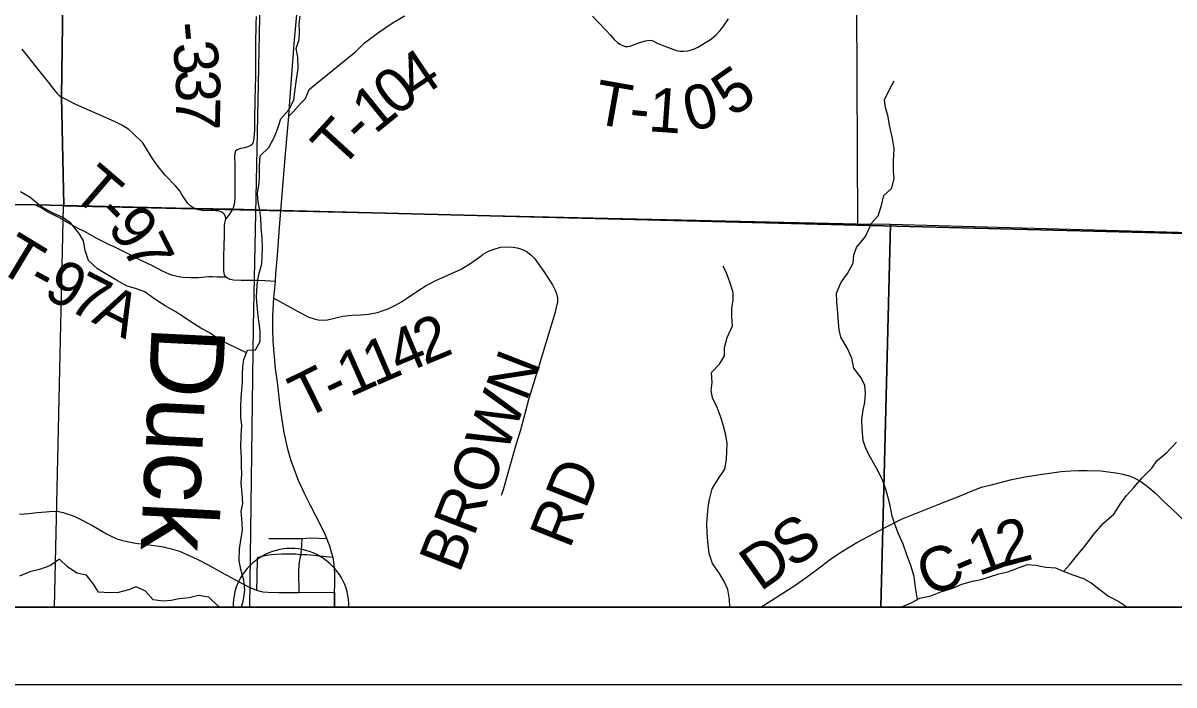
# Model space of a CAD drawing. Extents: x 0 to 34, y 0 to 22.
# Drawn here: x 26.994 to 28.471, y 14 to 14.85 of the extents above; entities that cross this region are included whole.
import ezdxf

# ---------------------------------------------------------------- set-up
doc = ezdxf.new("R2010")
doc.units = 0
for name, color, linetype in [('GM_X_Corporation', 7, 'Continuous'), ('GM_X_Corporation_Text', 7, 'Continuous'), ('GM_X_County_Road', 7, 'Continuous'), ('GM_X_County_Road_Text', 7, 'Continuous'), ('GM_X_Minor_River', 7, 'Continuous'), ('GM_X_Minor_River_Text', 7, 'Continuous'), ('GM_X_Rail_Line', 7, 'Continuous'), ('GM_X_State_Route', 7, 'Continuous'), ('GM_X_Township_Road', 7, 'Continuous'), ('GM_X_Township_Road_Text', 7, 'Continuous'), ('GM_X_Unincorporated_Location', 7, 'Continuous'), ('SH_Data', 7, 'Continuous')]:
    doc.layers.add(name, color=color, linetype=linetype)

msp = doc.modelspace()

# ---------------------------------------------------------------- linework, layer by layer
at = {"layer": 'GM_X_Corporation'}
for points in [[(26.6535, 14.621), (27.01, 14.6164), (27.046, 14.6155), (27.043, 14.755), (27.052, 15.403), (27.0676, 16.5549), (27.0694, 16.6556), (27.0775, 16.888), (27.0944, 18.0731), (27.1039, 18.5696), (27.1064, 18.6537), (27.3971, 18.6436), (28.3421, 18.6121), (28.7772, 18.6028), (29.0074, 18.5935), (29.6561, 18.5791), (29.6772, 18.5786), (30.101, 18.5701), (30.3167, 18.565), (30.3167, 20.9), (23.5167, 20.9)], [(23.5167, 14.1), (30.3167, 14.1), (30.3167, 18.565), (30.101, 18.5701), (29.6772, 18.5786), (29.6561, 18.5791), (29.0074, 18.5935), (28.7772, 18.6028), (28.3421, 18.6121), (27.3971, 18.6436), (27.1064, 18.6537), (27.1039, 18.5696), (27.0944, 18.0731), (27.0775, 16.888), (27.0694, 16.6556), (27.0676, 16.5549), (27.052, 15.403), (27.043, 14.755), (27.046, 14.6155), (27.01, 14.6164), (26.6535, 14.621)], [(27.0676, 16.5549), (27.052, 15.403), (27.043, 14.755), (27.046, 14.6155), (27.2076, 14.6118), (27.2151, 14.6117), (27.2601, 14.6106), (27.262, 14.6106), (27.3217, 14.6092), (27.3244, 14.6092), (28.7538, 14.5726), (28.7592, 14.5724), (28.9743, 14.568), (28.9779, 14.5679), (28.9904, 14.5676), (29.257, 14.5621), (29.2606, 14.562), (30.0913, 14.5411), (30.0947, 14.5411), (30.3167, 14.5373), (30.3167, 18.565)], [(26.6535, 14.621), (27.01, 14.6164), (27.046, 14.6155), (27.043, 14.755), (27.052, 15.403), (27.0676, 16.5549), (27.0694, 16.6556), (26.3378, 16.673)], [(26.0358, 14.1), (30.3167, 14.1), (30.3167, 14.5373), (30.0947, 14.5411), (30.0913, 14.5411), (29.2606, 14.562), (29.257, 14.5621), (28.9904, 14.5676), (28.9779, 14.5679), (28.9743, 14.568), (28.7592, 14.5724), (28.7538, 14.5726), (27.3244, 14.6092), (27.3217, 14.6092), (27.262, 14.6106), (27.2601, 14.6106), (27.2151, 14.6117), (27.2076, 14.6118), (27.046, 14.6155), (27.01, 14.6164), (26.6535, 14.621)]]:
    msp.add_lwpolyline(points, dxfattribs=at)
for points in [[(29.0554, 15.5858), (29.0455, 14.5648), (28.107, 14.591), (28.0653, 14.5914), (28.0603, 15.6194)], [(27.0339, 14.1), (28.0946, 14.1), (28.107, 14.591), (28.0653, 14.5914), (27.0453, 14.6145)], [(28.0946, 14.1), (29.1022, 14.1), (29.1115, 14.5644), (29.0455, 14.5648), (28.107, 14.591)]]:
    msp.add_lwpolyline(points, close=True, dxfattribs=at)
at = {"layer": 'GM_X_Corporation_Text'}
msp.add_line((27.2633, 14.1), (27.4121, 14.1), dxfattribs=at)
msp.add_arc((27.3377, 14.1008), 0.0744, 359.3562, 180.6438, dxfattribs=at)
at = {"layer": 'GM_X_County_Road'}
msp.add_line((27.3937, 14.1192), (27.3935, 14.1), dxfattribs=at)
for points in [[(27.9405, 14.1), (27.9842, 14.1276), (28.0004, 14.1392), (28.0188, 14.1529), (28.0299, 14.1613), (28.0406, 14.1687), (28.0517, 14.1758), (28.0638, 14.1831), (28.0991, 14.2019), (28.1213, 14.2127), (28.1403, 14.2206), (28.1681, 14.2318), (28.1997, 14.2439), (28.2119, 14.2493), (28.224, 14.2538), (28.2378, 14.2574), (28.2626, 14.2638), (28.2799, 14.2671), (28.2962, 14.2699), (28.3259, 14.2739), (28.3385, 14.2748), (28.3486, 14.2754), (28.3594, 14.2754), (28.3771, 14.2747), (28.396, 14.2723), (28.4053, 14.2704), (28.4131, 14.2683), (28.4199, 14.2657), (28.4283, 14.2611), (28.4385, 14.2535), (28.4465, 14.2466), (28.4576, 14.2357), (28.4674, 14.2264), (28.4869, 14.2081)], [(26.9891, 14.2192), (27.0011, 14.2203), (27.012, 14.2213), (27.0229, 14.2223), (27.0327, 14.223), (27.0395, 14.2225), (27.0454, 14.2213), (27.0502, 14.2199), (27.0555, 14.2179), (27.0601, 14.2162), (27.0645, 14.2143), (27.0821, 14.2052), (27.1011, 14.1942), (27.1077, 14.1904), (27.1143, 14.1874), (27.1202, 14.1857), (27.1275, 14.184), (27.1383, 14.1821), (27.1524, 14.1802), (27.1713, 14.1776), (27.1828, 14.1753), (27.1945, 14.1717), (27.2033, 14.1678), (27.2172, 14.1613), (27.2312, 14.1541), (27.248, 14.1449), (27.2609, 14.1378), (27.2749, 14.1303), (27.2839, 14.1255), (27.2934, 14.1218), (27.2976, 14.1204), (27.302, 14.1195), (27.308, 14.1191), (27.3217, 14.1185), (27.348, 14.1186), (27.3937, 14.1192)]]:
    msp.add_lwpolyline(points, dxfattribs=at)
at = {"layer": 'GM_X_Minor_River'}
for points in [[(27.2743, 14.1), (27.2768, 14.1092), (27.2783, 14.1217), (27.2771, 14.1346), (27.2733, 14.1483), (27.271, 14.16), (27.2717, 14.1744), (27.2735, 14.1858), (27.2754, 14.1983), (27.275, 14.2078), (27.2738, 14.2233), (27.2757, 14.2328), (27.2752, 14.2457), (27.2737, 14.2593), (27.2744, 14.2703), (27.274, 14.281), (27.274, 14.2912), (27.2735, 14.3056), (27.2739, 14.3204), (27.2746, 14.3337), (27.2734, 14.3435), (27.2734, 14.3568), (27.2737, 14.3685), (27.2745, 14.3784), (27.2756, 14.3886), (27.2755, 14.3985), (27.2759, 14.4083), (27.277, 14.4178), (27.2819, 14.4296), (27.2921, 14.4304), (27.2981, 14.441), (27.2981, 14.4547), (27.2969, 14.4645), (27.2954, 14.474), (27.2942, 14.4865), (27.2934, 14.4979), (27.2941, 14.5138), (27.2964, 14.5271), (27.3001, 14.5407), (27.3008, 14.551), (27.3012, 14.5612), (27.3008, 14.573), (27.2996, 14.5874), (27.2988, 14.5995), (27.2976, 14.6094), (27.2957, 14.62), (27.2945, 14.6309), (27.2968, 14.6442), (27.2971, 14.6537), (27.2971, 14.6662), (27.2982, 14.6791), (27.3091, 14.6898), (27.3167, 14.7034), (27.3208, 14.7148), (27.3245, 14.7266), (27.3347, 14.7384), (27.3415, 14.7505), (27.3426, 14.7619), (27.3448, 14.7771), (27.3467, 14.7915), (27.3466, 14.8059), (27.3443, 14.8169), (27.3481, 14.8286), (27.3484, 14.8393), (27.348, 14.8487), (27.3495, 14.8586)], [(28.1416, 14.1098), (28.1393, 14.1251), (28.1373, 14.1391), (28.1331, 14.1532), (28.1278, 14.1672), (28.1232, 14.1808), (28.1171, 14.194), (28.1125, 14.2065), (28.1091, 14.2168), (28.1064, 14.2304), (28.1037, 14.2418), (28.1006, 14.2528), (28.096, 14.2652), (28.0892, 14.2785), (28.0812, 14.2921), (28.0759, 14.3027), (28.072, 14.3133), (28.0705, 14.3292), (28.0701, 14.3402), (28.0719, 14.3531), (28.0742, 14.3626), (28.0749, 14.3747), (28.0741, 14.3842), (28.0695, 14.3941), (28.06, 14.4065), (28.0573, 14.4194), (28.0512, 14.4327), (28.0433, 14.4463), (28.0413, 14.4558), (28.0402, 14.4652), (28.0394, 14.4777), (28.0382, 14.4918), (28.0378, 14.5031), (28.0434, 14.5164), (28.0517, 14.5282), (28.0589, 14.5415), (28.06, 14.5521), (28.0634, 14.5616), (28.0751, 14.5757), (28.0826, 14.5928), (28.0913, 14.6023), (28.0954, 14.6156), (28.0984, 14.6281), (28.1086, 14.6376), (28.1116, 14.6501), (28.1108, 14.6596), (28.1107, 14.6729), (28.1118, 14.6888), (28.1095, 14.7013), (28.1057, 14.7187), (28.1041, 14.7293), (28.1007, 14.7411), (28.0995, 14.7509), (28.1055, 14.7634), (28.1116, 14.7756)], [(27.0182, 14.6132), (27.0152, 14.6156), (27.0029, 14.6256), (26.9906, 14.6328)], [(27.2806, 14.4265), (27.2591, 14.4367), (27.2444, 14.4443), (27.2341, 14.4514), (27.222, 14.4582), (27.2106, 14.4654), (27.1996, 14.4725), (27.189, 14.4793), (27.1761, 14.4865), (27.1617, 14.4959), (27.1503, 14.5046), (27.1381, 14.5091), (27.1275, 14.5121), (27.1131, 14.52), (27.1014, 14.5268), (27.0892, 14.5343), (27.0778, 14.5449), (27.0736, 14.5578), (27.0713, 14.5699), (27.066, 14.5797), (27.0546, 14.5934), (27.0451, 14.6001), (27.0326, 14.6058), (27.0182, 14.6132)], [(27.9008, 14.1), (27.9008, 14.1004), (27.9004, 14.1099), (27.8981, 14.1224), (27.8935, 14.133), (27.8874, 14.1432), (27.8787, 14.156), (27.8741, 14.1689), (27.8725, 14.1841), (27.8717, 14.1955), (27.8713, 14.2072), (27.872, 14.2182), (27.8731, 14.2281), (27.8746, 14.2379), (27.878, 14.2516), (27.8855, 14.2637), (27.8946, 14.2771), (27.8964, 14.2896), (27.8968, 14.2998), (27.8975, 14.31), (27.8956, 14.3207), (27.8929, 14.332), (27.8898, 14.3426), (27.8845, 14.3563), (27.8784, 14.3687), (27.8769, 14.3782), (27.878, 14.3881), (27.8772, 14.401), (27.8877, 14.412), (27.8938, 14.4223), (27.8941, 14.4332), (27.8975, 14.4462), (27.9043, 14.461), (27.9035, 14.4727), (27.9034, 14.4833), (27.9049, 14.4943), (27.9053, 14.5038), (27.9014, 14.5159), (27.8969, 14.5277), (27.8923, 14.5375)], [(28.3294, 14.1459), (28.3372, 14.1546), (28.3474, 14.1676), (28.3568, 14.1786), (28.3681, 14.1938), (28.3802, 14.2075), (28.3938, 14.2193), (28.4028, 14.2334), (28.41, 14.2432), (28.4194, 14.2535), (28.43, 14.2661), (28.4425, 14.2782), (28.4489, 14.2877), (28.4617, 14.2984), (28.4742, 14.3117)], [(27.2461, 14.1), (27.2442, 14.1011), (27.2321, 14.1129), (27.2188, 14.1147), (27.2071, 14.112), (27.1942, 14.1105), (27.184, 14.1085), (27.1738, 14.1077), (27.1609, 14.1092), (27.151, 14.1205), (27.1389, 14.1262), (27.1291, 14.122), (27.1162, 14.1189), (27.1049, 14.1181), (27.0908, 14.1192), (27.0844, 14.1294), (27.0753, 14.1408), (27.0628, 14.1434), (27.051, 14.1517), (27.0407, 14.1615), (27.0283, 14.1531), (27.015, 14.1481), (27.0025, 14.1454), (26.9893, 14.1397)], [(28.1212, 14.1), (28.1215, 14.1004), (28.1336, 14.1054), (28.1446, 14.1115), (28.1586, 14.1146), (28.1718, 14.1195), (28.1858, 14.1238), (28.1987, 14.1295), (28.2123, 14.1333), (28.2233, 14.1353), (28.2342, 14.1387), (28.246, 14.1426), (28.2577, 14.1453), (28.2721, 14.1506), (28.2827, 14.1548), (28.2933, 14.1537), (28.3065, 14.1511), (28.3186, 14.1504), (28.3285, 14.1463), (28.341, 14.1414), (28.3547, 14.1365), (28.3645, 14.1312), (28.3744, 14.1233), (28.3869, 14.1139), (28.4002, 14.1071), (28.4104, 14.1003), (28.4112, 14.1)]]:
    msp.add_lwpolyline(points, dxfattribs=at)
at = {"layer": 'GM_X_Rail_Line'}
msp.add_lwpolyline([(27.2849, 14.1), (27.2894, 14.4603), (27.296, 14.7712), (27.3019, 15.0727), (27.3033, 15.1457), (27.3034, 15.1975), (27.3156, 15.2527), (27.342, 15.317), (27.3625, 15.3837), (27.3871, 15.4458), (27.4012, 15.4983), (27.4051, 15.5497), (27.4044, 15.6175), (27.3887, 15.6715), (27.3693, 15.7118), (27.3529, 15.7652), (27.3562, 15.8103), (27.3646, 15.8502), (27.3938, 15.9037), (27.407, 16.0055), (27.4058, 16.0745), (27.3982, 16.1548), (27.3854, 16.3634)], dxfattribs=at)
at = {"layer": 'GM_X_State_Route'}
msp.add_line((27.3935, 14.1), (27.3937, 14.1192), dxfattribs=at)
for points in [[(27.3191, 14.537), (27.3203, 14.5516), (27.3228, 14.5871), (27.3246, 14.6086), (27.3301, 14.6767), (27.3348, 14.7301), (27.3353, 14.7379), (27.3418, 14.823), (27.3466, 14.8746)], [(27.3177, 14.5179), (27.3183, 14.5282), (27.3191, 14.537)], [(27.3937, 14.1192), (27.394, 14.1286), (27.3938, 14.1436), (27.3931, 14.1546), (27.3916, 14.1638), (27.3901, 14.1688), (27.3876, 14.1781), (27.386, 14.1823), (27.3837, 14.188), (27.3802, 14.196), (27.3693, 14.2178), (27.3623, 14.2314), (27.3552, 14.2457), (27.3475, 14.2623), (27.3438, 14.2715), (27.3376, 14.2891), (27.3337, 14.3025), (27.3288, 14.3239), (27.3262, 14.3404), (27.324, 14.358), (27.3202, 14.3888), (27.3188, 14.4004), (27.3178, 14.4064), (27.3148, 14.4413), (27.3143, 14.4563), (27.3142, 14.4737), (27.3155, 14.4964), (27.3177, 14.5179)]]:
    msp.add_lwpolyline(points, dxfattribs=at)
at = {"layer": 'GM_X_Township_Road'}
for points in [[(27.3348, 14.7301), (27.3406, 14.7356), (27.3507, 14.7471), (27.3562, 14.753), (27.361, 14.7644), (27.3708, 14.7725), (27.3844, 14.7836), (27.4208, 14.8131), (27.4317, 14.824), (27.4488, 14.8366), (27.4675, 14.8496), (27.4834, 14.8588)], [(27.7246, 14.8586), (27.742, 14.8402), (27.7475, 14.8339), (27.7525, 14.8285), (27.7567, 14.8247), (27.7597, 14.8226), (27.7624, 14.8212), (27.767, 14.8196), (27.77, 14.8194), (27.7728, 14.8201), (27.775, 14.8207), (27.7827, 14.8238), (27.7877, 14.8256), (27.7926, 14.827), (27.7977, 14.8275), (27.8011, 14.8271), (27.8046, 14.8257), (27.8085, 14.8236), (27.8175, 14.8199), (27.8277, 14.816), (27.8323, 14.8145), (27.8368, 14.8137), (27.8419, 14.8136), (27.8468, 14.814), (27.8516, 14.8151), (27.8557, 14.8165), (27.8596, 14.8186), (27.8762, 14.8287), (27.88, 14.8315), (27.8834, 14.8344), (27.8876, 14.8392), (27.8905, 14.8428), (27.8934, 14.8471), (27.8992, 14.8552)], [(27.2928, 14.8579), (27.2925, 14.8494), (27.2922, 14.821), (27.2922, 14.8097), (27.292, 14.7962), (27.2923, 14.7878), (27.2921, 14.779), (27.2916, 14.7685), (27.2911, 14.7489), (27.2908, 14.7272), (27.2907, 14.7124), (27.2901, 14.7019), (27.289, 14.6968), (27.2877, 14.6939), (27.2862, 14.6924), (27.2824, 14.6909), (27.2781, 14.6896), (27.2735, 14.6887), (27.2685, 14.6871), (27.2665, 14.6854), (27.2655, 14.6823), (27.2651, 14.6793), (27.2657, 14.6673), (27.2656, 14.6415), (27.2656, 14.631), (27.2655, 14.6239), (27.2652, 14.6205), (27.2646, 14.6166), (27.2634, 14.6126), (27.2622, 14.6101), (27.2586, 14.6042), (27.2539, 14.5982)], [(26.9921, 14.8162), (26.9976, 14.8095), (27.0043, 14.8013), (27.0153, 14.7871), (27.023, 14.7776), (27.0332, 14.7643), (27.0349, 14.7623), (27.0371, 14.7597), (27.0399, 14.757), (27.0432, 14.7545)], [(27.2116, 14.6131), (27.2078, 14.6155), (27.2055, 14.6181), (27.1969, 14.6308), (27.1944, 14.6345), (27.1894, 14.6409), (27.1762, 14.6546), (27.1672, 14.6655), (27.1615, 14.6734), (27.1568, 14.6804), (27.1475, 14.6959), (27.1352, 14.708), (27.1294, 14.7131), (27.1207, 14.7185), (27.1113, 14.7231), (27.0792, 14.7374), (27.0617, 14.745), (27.0432, 14.7545)], [(27.0102, 14.6158), (27.0183, 14.612), (27.0231, 14.609), (27.0283, 14.6062), (27.042, 14.599), (27.0514, 14.5938), (27.0633, 14.5868), (27.0724, 14.5824), (27.0891, 14.573), (27.0983, 14.5683), (27.1039, 14.5656), (27.1095, 14.5632), (27.1249, 14.5557), (27.1477, 14.5442), (27.158, 14.5393), (27.1668, 14.5346), (27.1722, 14.5318), (27.1769, 14.5296), (27.1819, 14.5274), (27.1858, 14.5261), (27.1897, 14.525), (27.1934, 14.5242), (27.196, 14.5238), (27.1987, 14.5235), (27.2083, 14.5231), (27.2187, 14.523), (27.2322, 14.5242), (27.2371, 14.5244), (27.2425, 14.524), (27.2485, 14.5239), (27.2537, 14.5241)], [(27.2539, 14.5982), (27.2535, 14.6014), (27.2518, 14.6044), (27.2489, 14.607), (27.2447, 14.6084), (27.2406, 14.6087), (27.2237, 14.6089), (27.2189, 14.6099), (27.2153, 14.6111), (27.2116, 14.6131)], [(27.3177, 14.5179), (27.3042, 14.5187), (27.2945, 14.5192), (27.2844, 14.5193), (27.2738, 14.5191), (27.2637, 14.5196), (27.2598, 14.5205), (27.2568, 14.5218), (27.2537, 14.5241), (27.252, 14.5277), (27.2513, 14.5326), (27.2514, 14.5402), (27.2516, 14.5493), (27.252, 14.5646), (27.2524, 14.5759), (27.2523, 14.5896), (27.2526, 14.5931), (27.2539, 14.5982)], [(27.3155, 14.4964), (27.3489, 14.4779), (27.3607, 14.4721), (27.3675, 14.4698), (27.3725, 14.4686), (27.3797, 14.4681), (27.3845, 14.4686), (27.3899, 14.4698), (27.3968, 14.4718), (27.4044, 14.4732), (27.4159, 14.4746), (27.4267, 14.4751), (27.437, 14.4758), (27.4487, 14.4783), (27.4559, 14.4806), (27.4624, 14.483), (27.4719, 14.4875), (27.4797, 14.4917), (27.4873, 14.497), (27.5005, 14.5061), (27.5113, 14.5127), (27.5234, 14.519), (27.5561, 14.5339), (27.5686, 14.5415), (27.5801, 14.5494), (27.5845, 14.5529), (27.5904, 14.5565), (27.5983, 14.5595), (27.6064, 14.5619), (27.6141, 14.5624), (27.6227, 14.5619), (27.6281, 14.5611), (27.6336, 14.5595), (27.6393, 14.5568), (27.6453, 14.5523), (27.6507, 14.5468), (27.662, 14.5306), (27.6731, 14.5137), (27.6762, 14.5076), (27.6783, 14.5023), (27.6796, 14.4964), (27.6795, 14.4918), (27.6781, 14.4845), (27.6765, 14.4785), (27.6655, 14.4417), (27.6543, 14.405), (27.6507, 14.3927), (27.6431, 14.3678), (27.632, 14.3271), (27.6266, 14.3095), (27.6142, 14.2657), (27.6098, 14.2503), (27.6074, 14.2431)], [(27.3091, 14.1881), (27.3519, 14.1879), (27.3624, 14.1887), (27.3735, 14.1884), (27.3837, 14.188)], [(27.3501, 14.167), (27.351, 14.1726), (27.3519, 14.1879)], [(27.3916, 14.1638), (27.3785, 14.1649), (27.3665, 14.1664), (27.3579, 14.1672), (27.3501, 14.167), (27.3441, 14.1678), (27.338, 14.1681), (27.3259, 14.1678), (27.3119, 14.1669), (27.302, 14.1653), (27.2942, 14.1632), (27.2938, 14.1381), (27.2934, 14.1218)], [(27.348, 14.1186), (27.3478, 14.1451), (27.3481, 14.155), (27.3501, 14.167)]]:
    msp.add_lwpolyline(points, dxfattribs=at)
at = {"layer": 'GM_X_Unincorporated_Location'}
msp.add_line((27.3377, 14.1008), (27.3377, 14.1008), dxfattribs=at)
at = {"layer": 'SH_Data'}
for points in [[(23.4167, 21), (30.4167, 21), (30.4167, 14), (23.4167, 14)], [(23.5167, 20.9), (30.3167, 20.9), (30.3167, 14.1), (23.5167, 14.1)]]:
    msp.add_lwpolyline(points, close=True, dxfattribs=at)

# ---------------------------------------------------------------- texts
at = {"layer": 'GM_X_County_Road_Text'}
for s, rotation, p in [('S', 35.6309, (27.9812, 14.1482)), ('2', 14.8516, (28.2513, 14.1513)), ('1', 20.662, (28.22, 14.1394)), ('D', 35.1168, (27.9398, 14.1191)), ('C', 23.1053, (28.1561, 14.1123)), ('-', 22.764, (28.199, 14.1305))]:
    msp.add_text(s, height=0.0568, rotation=rotation, dxfattribs=at).set_placement(p)
at = {"layer": 'GM_X_Minor_River_Text'}
msp.add_text('Duck', height=0.0947, rotation=267.1501, dxfattribs=at).set_placement((27.1591, 14.4622))
at = {"layer": 'GM_X_Township_Road_Text'}
for s, height, rotation, p in [('-', 0.0568, 275.0908, (27.1824, 14.8493)), ('3', 0.0568, 278.5086, (27.1849, 14.8224)), ('4', 0.0568, 33.9888, (27.4987, 14.7494)), ('3', 0.0568, 270.6974, (27.1899, 14.7899)), ('0', 0.0568, 38.9321, (27.4725, 14.7282)), ('5', 0.0568, 35.045, (27.904, 14.7277)), ('T', 0.0568, 349.9719, (27.7237, 14.7213)), ('0', 0.0568, 13.4942, (27.8489, 14.71)), ('1', 0.0568, 39.0759, (27.4454, 14.7061)), ('1', 0.0568, 355.9871, (27.7952, 14.7109)), ('7', 0.0568, 268.6989, (27.1904, 14.7554)), ('T', 0.0568, 47.607, (27.4013, 14.6603)), ('-', 0.0568, 354.5167, (27.7704, 14.7133)), ('-', 0.0568, 43.1396, (27.4292, 14.6909)), ('T', 0.0568, 319.3043, (27.0541, 14.6292)), ('-', 0.0568, 314.6909, (27.0855, 14.6023)), ('9', 0.0568, 307.2269, (27.1006, 14.5872)), ('T', 0.0568, 328.7628, (26.9578, 14.534)), ('7', 0.0568, 297.091, (27.1204, 14.5616)), ('9', 0.0568, 332.2211, (27.0179, 14.499)), ('-', 0.0568, 331.7007, (26.9969, 14.5104)), ('7', 0.0568, 332.6839, (27.0493, 14.4825)), ('A', 0.0568, 332.8402, (27.0806, 14.4664)), ('2', 0.0568, 22.4633, (27.5091, 14.4102)), ('4', 0.0568, 22.6103, (27.4768, 14.3968)), ('1', 0.0568, 23.1186, (27.4448, 14.3831)), ('1', 0.0568, 23.9878, (27.413, 14.369)), ('BROWN', 0.05682, 68.739, (27.5537, 14.142)), ('T', 0.0568, 26.3312, (27.3543, 14.3405)), ('-', 0.0568, 25.1197, (27.3921, 14.3592)), ('RD', 0.05682, 68.289, (27.6952, 14.1734))]:
    msp.add_text(s, height=height, rotation=rotation, dxfattribs=at).set_placement(p)

doc.saveas('drawing.dxf')
